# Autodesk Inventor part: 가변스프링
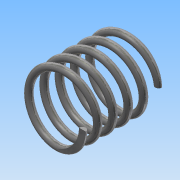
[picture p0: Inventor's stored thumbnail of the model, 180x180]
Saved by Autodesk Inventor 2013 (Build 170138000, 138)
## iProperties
Created: 2017-12
Part Number: 가변스프링
Material: 스테인리스강
Document SubType Name: Modeling
Designer: Administrator
Density: 8.08 g/cm^3
Mass: 7.0754 g
Surface Area: 17.7406 cm^2
Volume: 0.875668 cm^3
Author: Administrator
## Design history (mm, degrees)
sketch "스케치1"
  geometry: L1 (0, 0)-(9, 0); L2 (0, 0)-(0, 28.5); L3 (0, 28.5)-(19.49, 28.5); C1 r 1 at (9, 0)
  constraints: 6 end point, 2 perpendicular, 1 centre point, 1 coincident, 1 horizontal
  dimensions: "d0" = 28.5 distance of L1.start L2.end (derived); "d1" = 9 distance of L1.start L1.end; "d2" = 2 diameter of C1
feature "코일1" sketch "스케치1" pitch "d3" = 10; turns "d5" = 5; dims "d4" = 28.5 (= d0), "d6" = 0, angle "d7" = 90 deg, angle "d8" = 90 deg, "d9" = 0, "d10" = 0
sketch "스케치2"
  geometry: L1 (0, 12.5)-(28.5, 12.5); L2 (28.5, 12.5)-(28.5, -12.5); L3 (28.5, -12.5)-(0, -12.5); L4 (0, -12.5)-(0, 12.5); 2 further points
  constraints: 8 end point, 2 parallel, 1 coincident, 1 horizontal, 1 midpoint, 1 perpendicular
  dimensions: "d11" = 25 distance of L1.end L2.end; "d13" = 28.5 distance of L1.start L1.end (derived)
extrude "돌출1" sketch "스케치2" stored distance "d14" = 30; taper "d15" = 0 deg
node "솔리드1"
